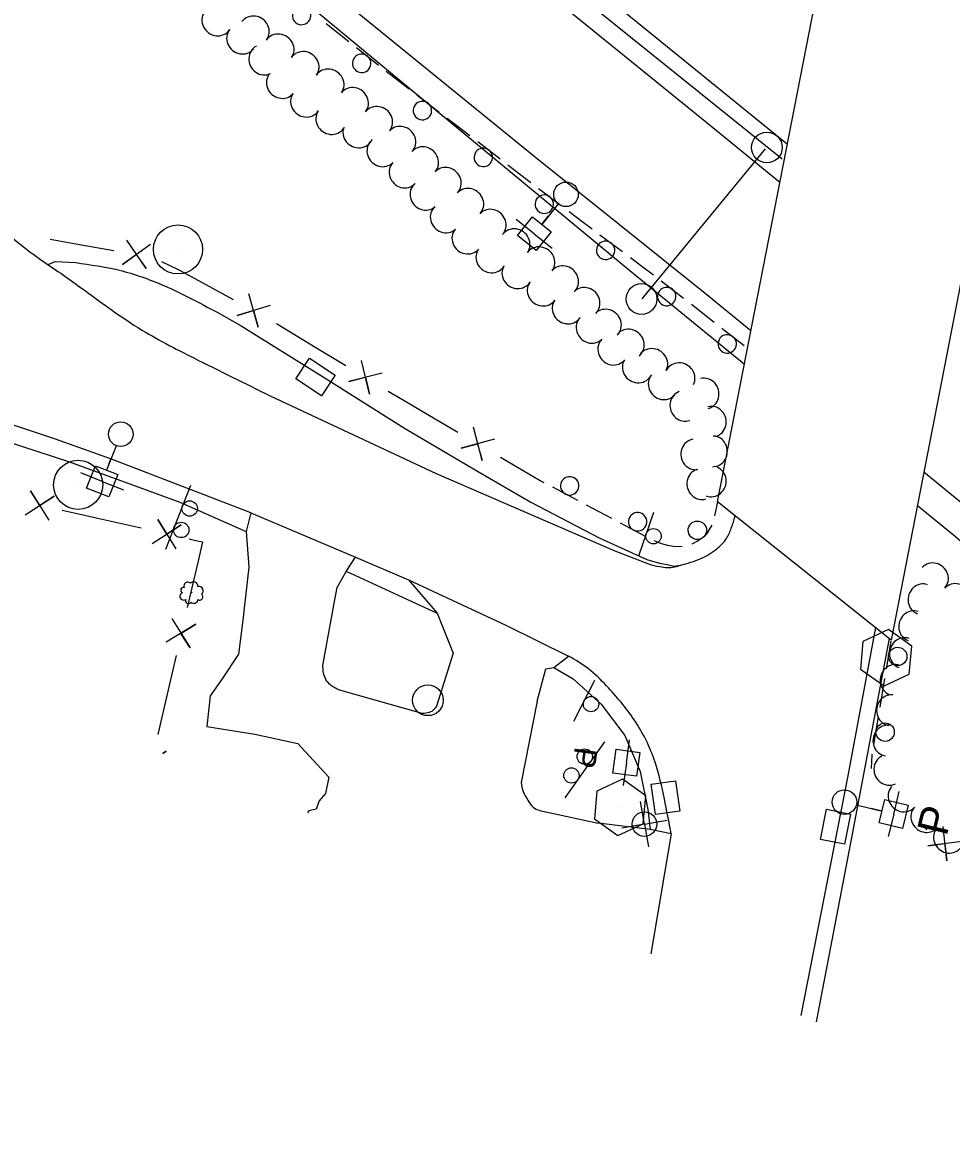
# Model space of a CAD drawing. Extents: x 1746010 to 1754829, y 655801 to 663091.
# Drawn here: x 1748767.9 to 1749070.2, y 660816.4 to 661182.3 of the extents above; entities that cross this region are included whole.
import ezdxf

# ---------------------------------------------------------------- set-up
doc = ezdxf.new("R2010")
doc.units = 0
for name, color, linetype in [('SURVEY - AERIAL SURVEY - Photo Control - Points - Elevations', 7, 'Continuous'), ('SURVEY - AERIAL SURVEY - Photo Control - Points - Locators', 7, 'Continuous'), ('SURVEY - AERIAL SURVEY - Photo Control - Points - Numbers', 7, 'Continuous'), ('SURVEY - AERIAL SURVEY - Photo Control with Text', 7, 'Continuous'), ('SURVEY - CENTERLINE - Existing Roads - Development', 7, 'Continuous'), ('SURVEY - CENTERLINE - Existing Roads Curve Text', 7, 'Continuous'), ('SURVEY - CENTERLINE - Existing Roads Text', 7, 'Continuous'), ('SURVEY - CENTERLINE - Preliminary - Development', 7, 'Continuous'), ('SURVEY - CENTERLINE - Preliminary Curve Text', 7, 'Continuous')]:
    doc.layers.add(name, color=color, linetype=linetype)

msp = doc.modelspace()

# ---------------------------------------------------------------- linework, layer by layer
at = {"layer": 'SURVEY - AERIAL SURVEY - Photo Control - Points - Elevations'}
msp.add_lwpolyline([(1749091.38, 661191), (1749050.62, 660981.19), (1748994.11, 661026.26), (1749035.04, 661236.3)], dxfattribs=at)
at = {"layer": 'SURVEY - AERIAL SURVEY - Photo Control - Points - Locators'}
for points in [[(1749014.37, 661130.26), (1748990.7, 661149.54), (1748916.31, 661209.97), (1748835.38, 661275.76), (1748731.71, 661360.72), (1748655.6, 661422.38), (1748555.07, 661504.4), (1748459.33, 661582.61), (1748380.29, 661646.59), (1748288.83, 661717.68), (1748181.12, 661800.02), (1748091.36, 661866.45), (1748036.84, 661905.72)], [(1749004.96, 661081.96), (1748990.07, 661094.14), (1748934.34, 661138.81), (1748865.88, 661194.6), (1748789.64, 661256.64), (1748729.69, 661305.4), (1748673.84, 661351.11), (1748595.91, 661414.43), (1748530.55, 661467.92), (1748473.83, 661514.17), (1748421, 661557.21), (1748361.81, 661604.95), (1748313.62, 661643.08), (1748341.85, 661611.66), (1748371.26, 661577.05), (1748408.51, 661529.92)], [(1749002.83, 661071), (1748965.52, 661101.51), (1748852.49, 661195.09), (1748776.59, 661254.93), (1748706.42, 661310.6), (1748625.44, 661375.29), (1748570.62, 661419.8), (1748495.86, 661480.71), (1748433.37, 661530.35), (1748414.07, 661545.49), (1748413.71, 661545.75)], [(1748523.79, 661544.26), (1748587.7, 661492.34), (1748672.29, 661423.24), (1748765.2, 661347.55), (1748850.45, 661278.14), (1748948.94, 661197.9), (1749016.8, 661142.7)], [(1748842.21, 661022.63), (1748822.81, 661030.17), (1748796.81, 661040.14), (1748778.58, 661046.61), (1748759.98, 661052.88), (1748736.59, 661060.44), (1748712.91, 661068.1), (1748688.81, 661074.54), (1748669.98, 661079.87), (1748648.34, 661085.22), (1748624.42, 661091.25), (1748598.28, 661097.15), (1748575.03, 661102), (1748553.53, 661106.02), (1748541.72, 661108.22)], [(1748541.72, 661108.22), (1748545.25, 661102.3), (1748592.74, 661092.3), (1748636.87, 661082.32), (1748679.9, 661071.09), (1748711.25, 661062), (1748742.12, 661052.58), (1748783.15, 661039.32), (1748819.11, 661026.13), (1748839.93, 661016.87), (1748840.62, 661016.6)], [(1748776.24, 661103.53), (1748778.47, 661104.56), (1748785.21, 661104.13)], [(1748831.2, 661087.97), (1748839.02, 661083.53), (1748865.2, 661067.27), (1748892.23, 661050.21), (1748916.5, 661035.92), (1748933.27, 661026.14), (1748955.6, 661014.49), (1748971.03, 661007.52), (1748975.19, 661006.32), (1748977.71, 661005.83), (1748979.92, 661005.33), (1748982.01, 661005.64)], [(1748848.74, 661060.68), (1748902.55, 661035.47), (1748960.6, 661010.28), (1748971.65, 661006.03)], [(1749328.25, 660820.51), (1749265.45, 660870.2), (1749186.55, 660933.71), (1749132.73, 660977.41), (1749077.4, 661022.72), (1749061.25, 661035.93)], [(1749311.71, 660816.35), (1749232.48, 660879.98), (1749122.79, 660969.99), (1749071.5, 661014.84), (1749059.12, 661024.96)], [(1748842.21, 661022.63), (1748840.62, 661016.6), (1748841.51, 661004.98), (1748839.45, 660986.84), (1748838.21, 660976.61), (1748832.8, 660968.6), (1748828.97, 660963.12), (1748827.86, 660953.06)], [(1748842.21, 661022.63), (1748876.2, 661008.27)], [(1748869.45, 660993.8), (1748870.3, 660998.39), (1748873.18, 661003.6), (1748876.2, 661008.27)], [(1748876.2, 661008.27), (1748893.46, 661000.84)], [(1748873.18, 661003.6), (1748874.58, 661003.05), (1748902.88, 660990.05)], [(1748893.46, 661000.84), (1748925.21, 660986.15), (1748945.62, 660976.04)], [(1748893.46, 661000.84), (1748902.88, 660990.05), (1748908.04, 660977.01)], [(1748865.65, 660972.93), (1748869.45, 660993.8)], [(1749045.45, 660985.32), (1749036.41, 660936.45), (1749021.16, 660859)], [(1749049.95, 660981.73), (1749037.91, 660918.04), (1749026.22, 660856.92)], [(1748908.04, 660977.01), (1748902.65, 660959.71)], [(1748935.33, 660961.36), (1748938.23, 660971.83), (1748940.78, 660972.35), (1748945.62, 660976.04)], [(1748940.78, 660972.35), (1748947.12, 660968.68), (1748956.21, 660960.39), (1748963.9, 660950.16), (1748968.91, 660938.46), (1748971.42, 660926.08), (1748972.19, 660919.57), (1748972.19, 660919.57)], [(1748897.99, 660957.29), (1748870.72, 660965.05)], [(1748935.33, 660961.36), (1748930.13, 660934.89)], [(1748827.86, 660953.06), (1748843.44, 660950.56), (1748857.46, 660947.56), (1748867.56, 660936.6), (1748866.52, 660931.33), (1748864.38, 660928.92), (1748863.41, 660926.17), (1748861.03, 660925.63), (1748860.61, 660924.99)], [(1748938.21, 660925.35), (1748955.24, 660921.67)], [(1748979, 660918.19), (1748972.19, 660919.57), (1748955.24, 660921.67)], [(1748979, 660918.19), (1748972.37, 660879.05)]]:
    msp.add_lwpolyline(points, dxfattribs=at)
for points in [[(1748742.62, 661133.3), (1748757.79, 661118.4), (1748768.18, 661109.29), (1748782.04, 661099.44), (1748805.67, 661082.87), (1748823.6, 661073.1), (1748848.74, 661060.68)], [(1748785.21, 661104.13), (1748799.4, 661101.66), (1748813.91, 661096.66), (1748831.2, 661087.97)], [(1748982.01, 661005.64), (1748988.67, 661007.78), (1748993.9, 661010.98), (1748996.96, 661014.3), (1748998.56, 661017.69), (1748999.82, 661021.7)], [(1748971.65, 661006.03), (1748975.3, 661005.15), (1748980.14, 661005.04), (1748982.22, 661005.71)], [(1748870.72, 660965.05), (1748867.76, 660966.94), (1748866.34, 660968.98), (1748865.76, 660971.15), (1748865.65, 660972.93)], [(1748979, 660918.19), (1748976.78, 660929.54), (1748973.77, 660941.5), (1748966.95, 660955.29), (1748957.94, 660966.34), (1748952.06, 660971.88), (1748945.62, 660976.04)], [(1748902.65, 660959.71), (1748901.77, 660958.59), (1748900.25, 660957.66), (1748897.99, 660957.29)], [(1748930.13, 660934.89), (1748930.84, 660931.92), (1748932.33, 660929.17), (1748934.07, 660926.83), (1748936.08, 660925.84), (1748938.21, 660925.35)]]:
    msp.add_spline(points, degree=3, dxfattribs=at)
at = {"layer": 'SURVEY - AERIAL SURVEY - Photo Control - Points - Numbers'}
for points in [[(1748040.01, 661910.33), (1748122.02, 661850.78), (1748195.38, 661796.53), (1748267.56, 661741.32), (1748333.52, 661690.82), (1748402.34, 661636.08), (1748451.04, 661597.23), (1748504.04, 661553.85), (1748559.78, 661508.8), (1748636.39, 661445.77), (1748709.27, 661386.44), (1748757.29, 661347.34), (1748822.35, 661294.7), (1748882.58, 661246), (1748955.33, 661186.03), (1749015.15, 661137.9)], [(1748866.7, 661182.04), (1748870.38, 661179.11)], [(1748870.38, 661179.11), (1748874.05, 661176.18)], [(1748876.56, 661174.19), (1748883.75, 661168.45)], [(1748886.26, 661166.46), (1748889.98, 661163.6)], [(1748889.98, 661163.6), (1748893.7, 661160.73)], [(1748896.24, 661158.78), (1748903.53, 661153.17)], [(1748906.06, 661151.21), (1748909.79, 661148.35)], [(1748909.79, 661148.35), (1748913.51, 661145.48)], [(1748916.05, 661143.53), (1748923.34, 661137.92)], [(1748925.87, 661135.96), (1748929.6, 661133.1)], [(1748929.6, 661133.1), (1748933.32, 661130.23)], [(1748935.86, 661128.28), (1748936.62, 661127.69), (1748943.2, 661122.74)], [(1748945.75, 661120.82), (1748949.51, 661117.99)], [(1748949.51, 661117.99), (1748953.26, 661115.17)], [(1748955.82, 661113.24), (1748963.16, 661107.71)], [(1748965.72, 661105.79), (1748969.47, 661102.97)], [(1748969.47, 661102.97), (1748973.23, 661100.14)], [(1748975.78, 661098.22), (1748976.17, 661097.93), (1748983.04, 661092.56)], [(1748985.56, 661090.59), (1748989.26, 661087.7)], [(1748989.26, 661087.7), (1748992.96, 661084.8)], [(1748995.48, 661082.83), (1748996.02, 661082.41), (1749002.71, 661077.15)], [(1748937.65, 661032.47), (1748936.39, 661033.14)], [(1748948.6, 661026.68), (1748940.48, 661030.98)], [(1748955.57, 661022.99), (1748951.42, 661025.19)], [(1748994.11, 661026.26), (1748993.04, 661021.69)], [(1748959.72, 661020.8), (1748955.57, 661022.99)], [(1748970.67, 661015.01), (1748962.55, 661019.31)], [(1748992.22, 661018.62), (1748991.39, 661017.26), (1748990.4, 661015.66), (1748989.13, 661014.38), (1748987.52, 661013.41), (1748985.69, 661012.5)], [(1748977.93, 661011.99), (1748977.77, 661012.01), (1748975.99, 661012.53), (1748974.59, 661013.1), (1748973.51, 661013.55)], [(1748982.6, 661011.73), (1748981.64, 661011.62), (1748979.61, 661011.72), (1748977.93, 661011.99)], [(1749049.06, 660971.85), (1749050.57, 660980.92)], [(1749047.77, 660964.07), (1749048.54, 660968.7)], [(1749047, 660959.45), (1749047.77, 660964.07)], [(1749044.96, 660947.23), (1749046.47, 660956.29)], [(1749044.18, 660939.4), (1749044.41, 660943.93), (1749044.44, 660944.08)]]:
    msp.add_lwpolyline(points, dxfattribs=at)
for centre, start, end in [((1748858.71, 661184.61), 164.4875, 164.4736), ((1748878.26, 661169.03), 164.4875, 164.4736), ((1748898.03, 661153.65), 165.4556, 165.4416), ((1748917.84, 661138.4), 165.4556, 165.4416), ((1748937.69, 661123.17), 166.0675, 166.0535), ((1748957.66, 661108.14), 166.0675, 166.0535), ((1748977.54, 661093.09), 165.0235, 165.0095), ((1748997.24, 661077.67), 164.9754, 164.9614), ((1748945.98, 661031.45), 355.3841, 355.3701), ((1748968.06, 661019.78), 355.3841, 355.3701), ((1748987.52, 661017), 68.3857, 68.3717), ((1749052.72, 660975.89), 283.5533, 283.5393), ((1749048.62, 660951.27), 283.5533, 283.5393)]:
    msp.add_arc(centre, 3, start, end, dxfattribs=at)
at = {"layer": 'SURVEY - AERIAL SURVEY - Photo Control with Text'}
for p, q in [((1748969.54, 661092.36), (1749009.64, 661141.17)), ((1749010.14, 661141.59), (1749010.14, 661141.59)), ((1748818.48, 661108.44), (1748818.48, 661108.44)), ((1748969.35, 661092.25), (1748969.35, 661092.25)), ((1748785.98, 661031.78), (1748785.98, 661031.78)), ((1748814.47, 661010.87), (1748822.64, 661031.73)), ((1748968.47, 661008.72), (1748973.31, 661022.92)), ((1749048.91, 660975.45), (1749048.91, 660975.45)), ((1748947.28, 660954.8), (1748954.13, 660968.14)), ((1748957.27, 660948.13), (1748944.35, 660929.83)), ((1748962.34, 660926.72), (1748962.34, 660926.72))]:
    msp.add_line(p, q, dxfattribs=at)
for points in [[(1749049.77, 660984.64), (1749041.4, 660980.76), (1749040.66, 660971.73), (1749048.26, 660966.37), (1749056.43, 660970.15), (1749057.37, 660979.28), (1749049.77, 660984.64)], [(1748963.19, 660935.91), (1748954.82, 660932.03), (1748954.08, 660923), (1748961.68, 660917.64), (1748969.86, 660921.42), (1748970.79, 660930.55), (1748963.19, 660935.91)]]:
    msp.add_lwpolyline(points, dxfattribs=at)
for centre, radius in [((1749010.14, 661141.63), 5), ((1748818.48, 661108.44), 8), ((1748969.34, 661092.29), 5), ((1748785.98, 661031.78), 8), ((1748822.27, 661024.08), 2.5), ((1748819.54, 661017.09), 2.5), ((1748973.23, 661015.07), 2.5), ((1748952.9, 660960.39), 2.5), ((1748950.86, 660943.3), 2.5), ((1748946.53, 660937.17), 2.5)]:
    msp.add_circle(centre, radius, dxfattribs=at)
at = {"layer": 'SURVEY - CENTERLINE - Existing Roads - Development'}
msp.add_line((1748899.8, 660961.6), (1748899.8, 660961.6), dxfattribs=at)
for points in [[(1748786.41, 661109.98), (1748776.83, 661111.67)], [(1748797.62, 661108), (1748786.41, 661109.98)], [(1748809.54, 661110.06), (1748800.39, 661103.55), (1748804.91, 661106.82), (1748808.16, 661102.18), (1748801.77, 661111.43)], [(1748826.5, 661097.52), (1748818.89, 661101.68), (1748813.19, 661104.39)], [(1748836.49, 661092.06), (1748826.5, 661097.52)], [(1748848.44, 661090.2), (1748837.7, 661086.96), (1748843.03, 661088.6), (1748844.62, 661083.17), (1748841.52, 661093.98)], [(1748863.32, 661076.42), (1748850.49, 661084.16)], [(1748873.07, 661070.54), (1748863.32, 661076.42)], [(1748884.93, 661068.17), (1748874.06, 661065.39), (1748879.45, 661066.81), (1748880.82, 661061.32), (1748878.17, 661072.24)], [(1748899.74, 661054.6), (1748891.51, 661059.42), (1748886.84, 661062.23)], [(1748909.57, 661048.84), (1748899.74, 661054.6)], [(1748921.46, 661046.62), (1748910.62, 661043.71), (1748916, 661045.19), (1748917.44, 661039.72), (1748914.65, 661050.61)], [(1748936.39, 661033.14), (1748923.45, 661040.71)], [(1748768.77, 661022.03), (1748778.22, 661028.12), (1748773.55, 661025.06), (1748770.52, 661029.82), (1748776.48, 661020.32)], [(1748780.79, 661023.56), (1748785.67, 661022.48), (1748791.88, 661021.06)], [(1748791.88, 661021.06), (1748806.44, 661017.74)], [(1748810.06, 661012.71), (1748819.55, 661018.74), (1748814.86, 661015.72), (1748811.89, 661020.49), (1748817.73, 661010.96)], [(1748822.06, 661014.18), (1748824.26, 661013.67), (1748826.43, 661013.22), (1748824.88, 661006.49)], [(1748824.88, 661006.49), (1748821.5, 660991.88)], [(1748816.44, 660988.22), (1748822.45, 660978.73), (1748819.44, 660983.43), (1748824.23, 660986.42), (1748814.66, 660980.52)], [(1748817.86, 660976.19), (1748815.29, 660965.09)], [(1748815.29, 660965.09), (1748811.91, 660950.48)], [(1748813.54, 660944.33), (1748814.65, 660945.03), (1748813.53, 660944.34)], [(1749062.21, 660919.5), (1749061.5, 660920.07)], [(1749073.69, 660915.62), (1749062.53, 660914.27), (1749068.07, 660914.98), (1749068.72, 660909.36), (1749067.5, 660920.54)]]:
    msp.add_lwpolyline(points, dxfattribs=at)
msp.add_circle((1748899.8, 660961.64), 5, dxfattribs=at)
at = {"layer": 'SURVEY - CENTERLINE - Existing Roads Curve Text'}
for p, q in [((1748942.31, 661123.34), (1748936.85, 661116.56)), ((1748937.11, 661116.88), (1748939.11, 661119.37)), ((1748934.41, 661113.53), (1748928.57, 661118.23)), ((1748934.41, 661113.53), (1748940.25, 661108.82)), ((1748798.41, 661044.66), (1748795.22, 661036.56)), ((1748795.37, 661036.94), (1748796.54, 661039.91)), ((1748793.79, 661032.93), (1748786.82, 661035.68)), ((1748793.79, 661032.93), (1748800.78, 661030.19)), ((1748964.4, 660941.28), (1748965.42, 660948.72)), ((1748964.4, 660941.28), (1748963.38, 660933.85)), ((1749051.41, 660924.6), (1749053.18, 660931.89)), ((1749039.17, 660927.58), (1749047.62, 660925.53)), ((1749047.23, 660925.62), (1749044.12, 660926.38)), ((1749051.41, 660924.6), (1749049.64, 660917.32))]:
    msp.add_line(p, q, dxfattribs=at)
for points in [[(1748928.93, 661112.93), (1748933.82, 661119.01), (1748939.89, 661114.12), (1748935, 661108.04)], [(1748788.74, 661030.73), (1748791.59, 661037.99), (1748798.85, 661035.14), (1748796, 661027.88)], [(1748968.79, 660944.62), (1748967.74, 660936.89), (1748960.01, 660937.95), (1748961.06, 660945.68)], [(1749054.28, 660919.9), (1749046.7, 660921.74), (1749048.54, 660929.32), (1749056.12, 660927.47)]]:
    msp.add_lwpolyline(points, close=True, dxfattribs=at)
for centre in [(1748944.76, 661126.38), (1748799.84, 661048.29), (1749035.38, 660928.5)]:
    msp.add_circle(centre, 4, dxfattribs=at)
at = {"layer": 'SURVEY - CENTERLINE - Existing Roads Text'}
msp.add_circle((1748822.93, 660996.67), 0.044, dxfattribs=at)
for centre, radius, start, end in [((1748820.23, 660997.52), 0.866, 69.8313, 248.5769), ((1748821.67, 660998.86), 1.26, 47.7151, 204.504), ((1748823.52, 660998.76), 1.44, 356.7679, 134.2921), ((1748825.29, 660997.29), 1.43, 307.6637, 103.5022), ((1748820.34, 660995.53), 1.26, 109.852, 303.2717), ((1748825.53, 660995.32), 1.05, 237.9166, 52.9169), ((1748821.88, 660994.04), 0.958, 152.4706, 329.7898), ((1748823.62, 660994.56), 1.36, 227.7577, 354.6034)]:
    msp.add_arc(centre, radius, start, end, dxfattribs=at)
for centre, major_axis in [((1748831.15, 661182.79), (-4.09, 2.88)), ((1748843.27, 661179.62), (4, -3)), ((1748839.19, 661176.89), (-3.89, 3.14)), ((1748851.35, 661173.78), (4.09, -2.87)), ((1748846.29, 661170.2), (-2.25, 4.47)), ((1748859.48, 661168.07), (4.09, -2.87)), ((1748867.62, 661162.35), (4.09, -2.87)), ((1748852.13, 661162.46), (-3.78, 3.28)), ((1748875.58, 661156.35), (3.93, -3.09)), ((1748860.02, 661156.35), (-4.12, 2.83)), ((1748883.45, 661150.17), (3.93, -3.09)), ((1748868.26, 661150.68), (-4.12, 2.83)), ((1748891.03, 661143.68), (3.71, -3.35)), ((1748877.1, 661146.27), (-4.61, 1.94)), ((1748884.84, 661140.23), (-3.61, 3.46)), ((1748898.43, 661137.01), (3.71, -3.35)), ((1748892.04, 661133.32), (-3.61, 3.46)), ((1748905.82, 661130.3), (3.65, -3.41)), ((1748898.82, 661126.08), (-3.34, 3.72)), ((1748913.12, 661123.48), (3.65, -3.41)), ((1748905.43, 661118.72), (-3.34, 3.72)), ((1748920.43, 661116.66), (3.65, -3.41)), ((1748928.14, 661110.33), (4.05, -2.94)), ((1748912.53, 661111.79), (-3.82, 3.23)), ((1748920.35, 661105.63), (-4.27, 2.6)), ((1748936.23, 661104.46), (4.05, -2.94)), ((1748928.82, 661100.47), (-4.27, 2.6)), ((1748944, 661098.25), (3.51, -3.56)), ((1748937.04, 661094.82), (-4.1, 2.86)), ((1748950.97, 661091.17), (3.51, -3.56)), ((1748945.17, 661089.02), (-4.04, 2.95)), ((1748952.92, 661082.75), (-3.52, 3.55)), ((1748957.93, 661084.1), (3.51, -3.56)), ((1748965.36, 661077.63), (3.84, -3.2)), ((1748959.97, 661075.65), (-3.52, 3.55)), ((1748972.95, 661071.39), (4.43, -2.32)), ((1748968.03, 661069.81), (-4.21, 2.7)), ((1748981.81, 661066.74), (4.43, -2.32)), ((1748976.4, 661064.35), (-3.83, 3.21)), ((1748989.83, 661061.52), (1.25, -4.84)), ((1748983.34, 661057.46), (-1.72, 4.7)), ((1748992.19, 661052.38), (1.25, -4.84)), ((1748986.86, 661041.7), (-0.84, 4.93)), ((1748992.56, 661042.69), (-0.15, -5)), ((1748988.85, 661031.99), (-1.47, 4.78)), ((1748992.16, 661032.83), (-1.82, -4.66)), ((1749064.35, 661001.53), (3.69, -3.37)), ((1749060.82, 660994.55), (1.64, 4.73)), ((1749071.73, 660994.8), (3.69, -3.37)), ((1749057.79, 660985.79), (1.64, 4.73)), ((1749054.76, 660977.04), (1.64, 4.73)), ((1749051.73, 660968.28), (1.64, 4.73)), ((1749050.54, 660958.41), (0.59, 4.96)), ((1749049.36, 660948.54), (0.59, 4.96)), ((1749049.74, 660938.92), (-2.21, 4.48)), ((1749054.45, 660930.17), (-3.7, 3.36)), ((1749061.85, 660923.45), (-3.7, 3.36)), ((1749069.25, 660916.72), (-3.7, 3.36))]:
    msp.add_ellipse(centre, major_axis=major_axis, ratio=0.940188, start_param=0, end_param=3.141593, dxfattribs=at)
at = {"layer": 'SURVEY - CENTERLINE - Preliminary - Development'}
for p, q in [((1748863.23, 661066.88), (1748863.23, 661066.88)), ((1748977.14, 660929.9), (1748977.14, 660929.9)), ((1749032.45, 660920.46), (1749032.45, 660920.46))]:
    msp.add_line(p, q, dxfattribs=at)
for points in [[(1748856.85, 661066.32), (1748861.28, 661072.98), (1748869.6, 661067.45), (1748865.18, 661060.78), (1748856.85, 661066.32)], [(1748972.49, 660934.31), (1748980.42, 660935.4), (1748981.78, 660925.49), (1748973.86, 660924.4), (1748972.49, 660934.31)], [(1749029.5, 660926.15), (1749037.34, 660924.59), (1749035.4, 660914.78), (1749027.55, 660916.34), (1749029.5, 660926.15)]]:
    msp.add_lwpolyline(points, dxfattribs=at)
at = {"layer": 'SURVEY - CENTERLINE - Preliminary Curve Text'}
for q in [(1748969.01, 660928.71), (1748977.67, 660922.6), (1748962.9, 660920.04), (1748971.57, 660913.94)]:
    msp.add_line((1748970.29, 660921.32), q, dxfattribs=at)
msp.add_circle((1748970.29, 660921.32), 4, dxfattribs=at)

# ---------------------------------------------------------------- texts
at = {"layer": 'SURVEY - CENTERLINE - Existing Roads Curve Text'}
for height, rotation, p in [(7.48, 262.207, (1748947.68, 660946.7)), (10, 76.3483, (1749068.63, 660917.13))]:
    msp.add_text('P', height=height, rotation=rotation, dxfattribs=at).set_placement(p)

doc.saveas('drawing.dxf')
